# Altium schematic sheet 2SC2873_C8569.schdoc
size 127 x 101 mm
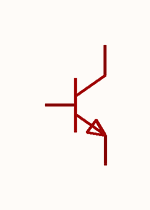
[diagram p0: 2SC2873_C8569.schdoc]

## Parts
Q?  2sc2873(range:120-240)  [SOT-89-3_L4.5-W2.5-P1.50-LS4.2-BR]  (value not drawn)

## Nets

Not connected (* = marked no-connect by the designer): Q? 1(B) 2(C) 3(E)

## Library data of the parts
Q? = 2sc2873(range:120-240): 晶体管类型:NPN;集电极电流(Ic):2A;集射极击穿电压(Vceo):50V;耗散功率(Pd):500mW;直流电流增益(hFE):120;; Manufacturer: CJ(江苏长电/长晶); Symbol: 2SC2873_C8569; AddInBom: yes; ModelId: 6db690b7897d4d18a30d90c1b89525ee; ModelName: SOT-89-3_L4.3-W2.5-H1.6-LS4.1-P1.50; ModelTransform: 161.417,169.291,0,180,0,0,-18.661,0,0; type: NPN; Current - Collector(Ic): 2A; Collector - Emitter Voltage VCEO: 50V; Pd - Power Dissipation: 500mW; DC Current Gain: 120; Transition frequency(fT): 120MHz; Current - Collector Cutoff: 100nA; Vce Saturation(VCE(sat)): 500mV; Emitter-Base Voltage(Vebo): 5V; Number: 1个NPN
